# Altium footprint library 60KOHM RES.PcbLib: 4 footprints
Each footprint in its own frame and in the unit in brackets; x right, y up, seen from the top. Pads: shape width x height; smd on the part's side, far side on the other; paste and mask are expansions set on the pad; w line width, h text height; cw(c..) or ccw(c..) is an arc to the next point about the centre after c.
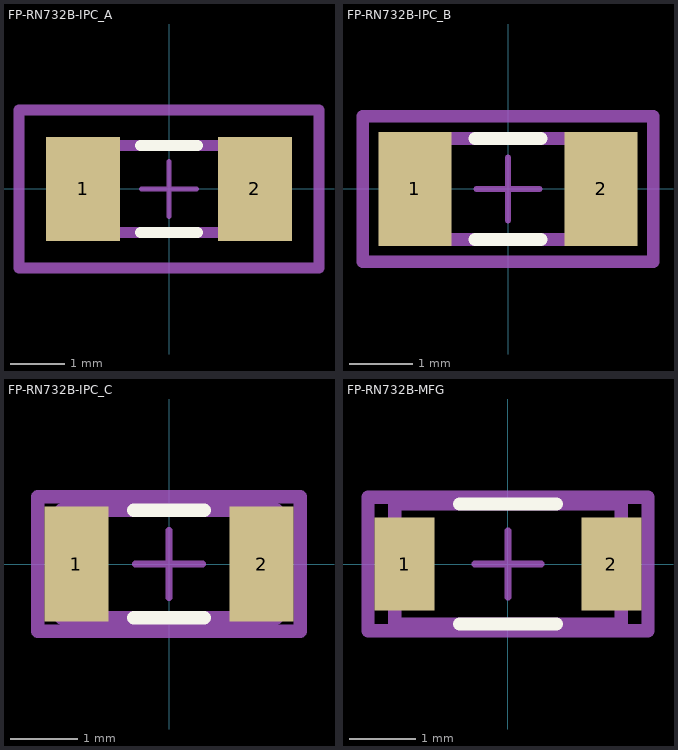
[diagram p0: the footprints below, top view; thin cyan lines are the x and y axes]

## FP-RN732B-IPC_A [mm]
pads (2):
  rect 1.355x1.906 smd paste+0 mask+0: 1(-1.575,0) 2(1.575,0)
Top Overlay:
  lines w0.2: -0.523,-0.8 0.523,-0.8 ; -0.523,0.8 0.523,0.8
Top Assembly:
  lines w0.2: -2.753,-1.453 2.753,-1.453 2.753,1.453 -2.753,1.453 -2.753,-1.453
  text ".Designator" at 0,0.188 h1
Top 3D Body:
  lines w0.2: -1.6,-0.8 1.6,-0.8 1.6,0.8 -1.6,0.8 -1.6,-0.8
Top Courtyard:
  lines w0.2: -2.753,-1.453 2.753,-1.453 2.753,1.453 -2.753,1.453 -2.753,-1.453
Top Component Center:
  lines w0.1: -0.5,0 0.5,0 ; 0,-0.5 0,0.5
3D body "Res_KOA_Speer_RN732BTTD1012A05_eec.STEP": height 0.25, standoff 0, extent -2.753,-1.453 2.753,1.453

## FP-RN732B-IPC_B [mm]
pads (2):
  rect 1.155x1.806 smd paste+0 mask+0: 1(-1.475,0) 2(1.475,0)
Top Overlay:
  lines w0.2: -0.523,-0.8 0.523,-0.8 ; -0.523,0.8 0.523,0.8
Top Assembly:
  lines w0.2: -2.303,-1.153 2.303,-1.153 2.303,1.153 -2.303,1.153 -2.303,-1.153
  text ".Designator" at 0,0.188 h1
Top 3D Body:
  lines w0.2: -1.6,-0.8 1.6,-0.8 1.6,0.8 -1.6,0.8 -1.6,-0.8
Top Courtyard:
  lines w0.2: -2.303,-1.153 2.303,-1.153 2.303,1.153 -2.303,1.153 -2.303,-1.153
Top Component Center:
  lines w0.1: -0.5,0 0.5,0 ; 0,-0.5 0,0.5
3D body "Res_KOA_Speer_RN732BTTD1012A05_eec.STEP": height 0.25, standoff 0, extent -2.303,-1.153 2.303,1.153

## FP-RN732B-IPC_C [mm]
pads (2):
  rect 0.955x1.706 smd paste+0 mask+0: 1(-1.375,0) 2(1.375,0)
Top Overlay:
  lines w0.2: -0.523,-0.8 0.523,-0.8 ; -0.523,0.8 0.523,0.8
Top Assembly:
  lines w0.2: -1.953,-1 1.953,-1 1.953,1 -1.953,1 -1.953,-1
  text ".Designator" at 0,0.188 h1
Top 3D Body:
  lines w0.2: -1.6,-0.8 1.6,-0.8 1.6,0.8 -1.6,0.8 -1.6,-0.8
Top Courtyard:
  lines w0.2: -1.953,-1 1.953,-1 1.953,1 -1.953,1 -1.953,-1
Top Component Center:
  lines w0.1: -0.5,0 0.5,0 ; 0,-0.5 0,0.5
3D body "Res_KOA_Speer_RN732BTTD1012A05_eec.STEP": height 0.25, standoff 0, extent -1.953,-1 1.953,1

## FP-RN732B-MFG [mm]
pads (2):
  rect 0.9x1.4 smd paste+0 mask+0: 1(-1.55,0) 2(1.55,0)
Top Overlay:
  lines w0.2: -0.725,-0.9 0.725,-0.9 ; -0.725,0.9 0.725,0.9
Top Assembly:
  lines w0.2: -2.1,-1 2.1,-1 2.1,1 -2.1,1 -2.1,-1
  text ".Designator" at 0,0.188 h1
Top 3D Body:
  lines w0.2: -1.7,-0.9 1.7,-0.9 1.7,0.9 -1.7,0.9 -1.7,-0.9
Top Courtyard:
  lines w0.2: -2.1,-1 2.1,-1 2.1,1 -2.1,1 -2.1,-1
Top Component Center:
  lines w0.1: -0.5,0 0.5,0 ; 0,-0.5 0,0.5
3D body "Res_KOA_Speer_RN732BTTD1012A05_eec.STEP": height 0.25, standoff 0, extent -2.1,-1 2.1,1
